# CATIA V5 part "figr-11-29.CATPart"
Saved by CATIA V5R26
Part number: Part1
Bounding box of the stored display mesh (mm): x -52 to 53, y -75.374 to 75.374, z 0 to 37.54
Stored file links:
  D:\_Deepak\CATIA\CATIA V5-6R2016_Deepak\Resources\Part files\Partfiles\c11_catia_v5_6r2016_prt\figr-11-29.CATPart
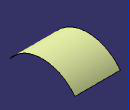
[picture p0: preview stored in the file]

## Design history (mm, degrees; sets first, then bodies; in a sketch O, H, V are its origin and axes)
Set1
  Extrude1: Element1 Sketch1, Lim1 53, Lim2 52, Direction yz-plane
Body1 (main body)
  Sketch1 on yz-plane, origin (0, 0, 0), H (0, 1, 0), V (0, 0, 1)
    arc A1 centre (0, -56.4477) radius 94.1675 from (-75.3736, 0) to (75.3736, 0) cw
    point P1 (0, -56.4477)
    point P2 (-75.3736, 0)
    point P3 (75.3736, 0)
    point P4 (0, 37.7198)
    coincidence: P2 H, P3 H, A1 P4, P4 V, P1 V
